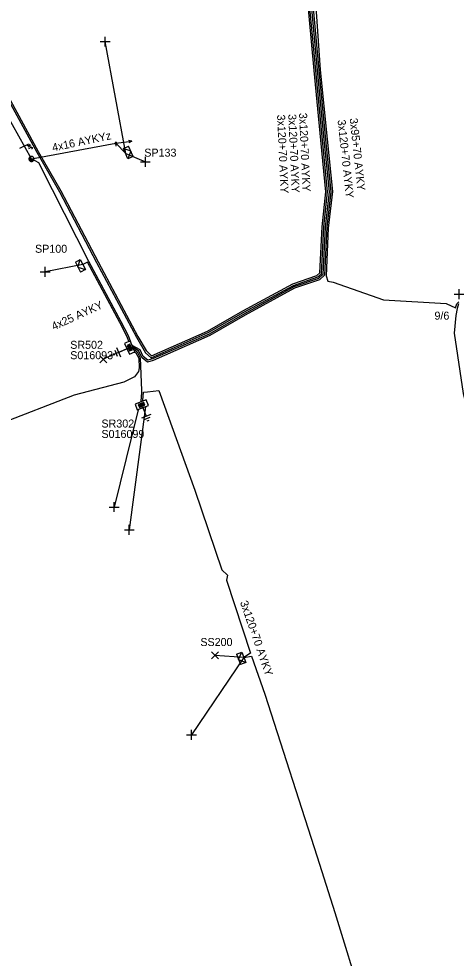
# Model space of a CAD drawing. Extents: x -717562 to -713845, y -1151196 to -1143903.
# Drawn here: x -717035.8 to -716981.2, y -1144669.5 to -1144552.1 of the extents above; entities that cross this region are included whole.
import ezdxf

# ---------------------------------------------------------------- set-up
doc = ezdxf.new("R2010")
doc.units = 0
for name, color, linetype in [('Vrstva 1', 7, 'Continuous'), ('Vrstva 12', 7, 'Continuous'), ('Vrstva 13', 7, 'Continuous'), ('Vrstva 14', 7, 'Continuous'), ('Vrstva 15', 7, 'Continuous'), ('Vrstva 18', 7, 'Continuous'), ('Vrstva 2', 7, 'Continuous'), ('Vrstva 28', 7, 'Continuous'), ('Vrstva 29', 7, 'Continuous'), ('Vrstva 30', 7, 'Continuous'), ('Vrstva 31', 7, 'Continuous'), ('Vrstva 33', 7, 'Continuous'), ('Vrstva 34', 7, 'Continuous'), ('Vrstva 5', 7, 'Continuous'), ('Vrstva 52', 7, 'Continuous'), ('Vrstva 54', 7, 'Continuous'), ('Vrstva 55', 7, 'Continuous'), ('Vrstva 59', 7, 'Continuous'), ('Vrstva 6', 7, 'Continuous'), ('Vrstva 8', 7, 'Continuous'), ('Vrstva 9', 7, 'Continuous')]:
    doc.layers.add(name, color=color, linetype=linetype)

# ---------------------------------------------------------------- blocks, each defined once
blk = doc.blocks.new('NN440')
at = {"layer": 'Vrstva 2'}
for points in [[(0.63, 0), (0.63, 0.06), (0.62, 0.13), (0.6, 0.19), (0.58, 0.25), (0.55, 0.31), (0.51, 0.37), (0.47, 0.42), (0.42, 0.46), (0.37, 0.51), (0.32, 0.54), (0.26, 0.57), (0.2, 0.59), (0.13, 0.61), (0.07, 0.62), (0, 0.63), (-0.06, 0.62), (-0.13, 0.61), (-0.19, 0.59), (-0.26, 0.57), (-0.31, 0.54), (-0.37, 0.51), (-0.42, 0.46), (-0.47, 0.42), (-0.51, 0.37), (-0.54, 0.31), (-0.57, 0.25), (-0.6, 0.19), (-0.62, 0.13), (-0.63, 0.06), (-0.63, 0), (-0.63, -0.07), (-0.62, -0.14), (-0.6, -0.2), (-0.57, -0.26), (-0.54, -0.32), (-0.51, -0.37), (-0.47, -0.43), (-0.42, -0.47), (-0.37, -0.51), (-0.31, -0.55), (-0.26, -0.58), (-0.19, -0.6), (-0.13, -0.62), (-0.06, -0.63), (0, -0.63), (0.07, -0.63), (0.13, -0.62), (0.2, -0.6), (0.26, -0.58), (0.32, -0.55), (0.37, -0.51), (0.42, -0.47), (0.47, -0.43), (0.51, -0.37), (0.55, -0.32), (0.58, -0.26), (0.6, -0.2), (0.62, -0.14), (0.63, -0.07), (0.63, 0)], [(-0.63, 0), (0.63, 0)], [(-0.6, -0.18), (0.57, -0.18)], [(-0.51, -0.32), (0.5, -0.32)], [(-0.37, -0.47), (0.35, -0.47)]]:
    blk.add_lwpolyline(points, dxfattribs=at)
blk = doc.blocks.new('NN560')
at = {"layer": 'Vrstva 2'}
for points in [[(2, 0), (1.59, 0.14)], [(0, 0), (2, 0)], [(2, 0), (1.59, -0.13)]]:
    blk.add_lwpolyline(points, dxfattribs=at)
blk = doc.blocks.new('NN840')
at = {"layer": 'Vrstva 15'}
for points in [[(0, 0.62), (0, -0.63)], [(-0.75, -0.71), (-0.75, -0.66)], [(-0.73, -0.76), (-0.75, -0.71)], [(-0.66, -0.8), (-0.73, -0.76)], [(-0.63, -0.8), (-0.66, -0.8)], [(-0.56, -0.76), (-0.63, -0.8)], [(-0.54, -0.71), (-0.56, -0.76)], [(-0.54, -0.38), (-0.54, -0.71)], [(-0.33, -0.38), (-0.33, -0.8)], [(-0.33, -0.64), (-0.13, -0.38)], [(-0.26, -0.56), (-0.09, -0.8)]]:
    blk.add_lwpolyline(points, dxfattribs=at)
blk = doc.blocks.new('NN800')
at = {"layer": 'Vrstva 1'}
for points in [[(-0.44, 0.44), (0.44, -0.44)], [(-0.44, -0.44), (0.44, 0.44)]]:
    blk.add_lwpolyline(points, dxfattribs=at)
blk = doc.blocks.new('NN620')
at = {"layer": 'Vrstva 8'}
for points in [[(0.75, 0), (-0.75, 0)], [(-0.75, 0), (-0.75, -0.75)], [(0.75, -0.75), (0.75, 0)], [(-0.75, -0.75), (0.75, -0.75)], [(0.37, -0.18), (-0.38, -0.18)], [(-0.38, -0.18), (-0.38, -0.56)], [(-0.38, -0.56), (0.37, -0.56)], [(0.32, -0.23), (-0.33, -0.23)], [(-0.33, -0.23), (-0.33, -0.51)], [(-0.33, -0.51), (0.32, -0.51)], [(0.27, -0.27), (-0.28, -0.27)], [(-0.28, -0.27), (-0.28, -0.46)], [(-0.28, -0.46), (0.27, -0.46)], [(0.23, -0.32), (-0.23, -0.32)], [(-0.23, -0.32), (-0.23, -0.42)], [(-0.23, -0.42), (0.23, -0.42)], [(-0.19, -0.37), (0.19, -0.37)], [(0.23, -0.42), (0.23, -0.32)], [(0.27, -0.46), (0.27, -0.27)], [(0.32, -0.51), (0.32, -0.23)], [(0.37, -0.56), (0.37, -0.18)]]:
    blk.add_lwpolyline(points, dxfattribs=at)
blk = doc.blocks.new('NN630')
at = {"layer": 'Vrstva 9'}
for points in [[(0, -0.7), (-0.7, 0)], [(-0.7, -0.7), (-0.7, 0), (0.7, 0), (0.7, -0.7)], [(-0.7, -0.7), (0.7, -0.7)], [(0, -0.7), (0.7, 0)]]:
    blk.add_lwpolyline(points, dxfattribs=at)
blk = doc.blocks.new('NN810')
at = {"layer": 'Vrstva 14'}
for points in [[(0, -0.64), (0, -1.89)], [(0.63, -1.89), (-0.62, -1.89)], [(0.39, -2.2), (-0.4, -2.2)], [(0, -2.52), (-0.12, -2.52)], [(0.14, -2.52), (0, -2.52)]]:
    blk.add_lwpolyline(points, dxfattribs=at)
blk = doc.blocks.new('NN500')
at = {"layer": 'Vrstva 2'}
for points in [[(0, -0.24), (0.02, -0.23), (0.05, -0.23), (0.07, -0.22), (0.09, -0.22), (0.12, -0.2), (0.14, -0.19), (0.16, -0.18), (0.17, -0.16), (0.19, -0.14), (0.2, -0.12), (0.21, -0.1), (0.22, -0.07), (0.23, -0.05), (0.23, -0.02), (0.23, 0), (0.23, 0.02), (0.23, 0.05), (0.22, 0.07), (0.21, 0.1), (0.2, 0.12), (0.19, 0.14), (0.17, 0.16), (0.16, 0.17), (0.14, 0.19), (0.12, 0.2), (0.09, 0.21), (0.07, 0.22), (0.05, 0.23), (0.02, 0.23), (0, 0.23), (-0.03, 0.23), (-0.05, 0.23), (-0.07, 0.22), (-0.1, 0.21), (-0.12, 0.2), (-0.14, 0.19), (-0.16, 0.17), (-0.18, 0.16), (-0.19, 0.14), (-0.2, 0.12), (-0.22, 0.1), (-0.22, 0.07), (-0.23, 0.05), (-0.23, 0.02), (-0.24, 0), (-0.23, -0.02), (-0.23, -0.05), (-0.22, -0.07), (-0.22, -0.1), (-0.2, -0.12), (-0.19, -0.14), (-0.18, -0.16), (-0.16, -0.18), (-0.14, -0.19), (-0.12, -0.2), (-0.1, -0.22), (-0.07, -0.22), (-0.05, -0.23), (-0.03, -0.23), (0, -0.24)], [(0, -0.24), (0.02, -0.23), (0.05, -0.23), (0.07, -0.22), (0.09, -0.22), (0.12, -0.2), (0.14, -0.19), (0.16, -0.18), (0.17, -0.16), (0.19, -0.14), (0.2, -0.12), (0.21, -0.1), (0.22, -0.07), (0.23, -0.05), (0.23, -0.02), (0.23, 0), (0.23, 0.02), (0.23, 0.05), (0.22, 0.07), (0.21, 0.1), (0.2, 0.12), (0.19, 0.14), (0.17, 0.16), (0.16, 0.17), (0.14, 0.19), (0.12, 0.2), (0.09, 0.21), (0.07, 0.22), (0.05, 0.23), (0.02, 0.23), (0, 0.23), (-0.03, 0.23), (-0.05, 0.23), (-0.07, 0.22), (-0.1, 0.21), (-0.12, 0.2), (-0.14, 0.19), (-0.16, 0.17), (-0.18, 0.16), (-0.19, 0.14), (-0.2, 0.12), (-0.22, 0.1), (-0.22, 0.07), (-0.23, 0.05), (-0.23, 0.02), (-0.24, 0), (-0.23, -0.02), (-0.23, -0.05), (-0.22, -0.07), (-0.22, -0.1), (-0.2, -0.12), (-0.19, -0.14), (-0.18, -0.16), (-0.16, -0.18), (-0.14, -0.19), (-0.12, -0.2), (-0.1, -0.22), (-0.07, -0.22), (-0.05, -0.23), (-0.03, -0.23), (0, -0.24)], [(0, -0.21), (0.02, -0.2), (0.04, -0.2), (0.06, -0.2), (0.08, -0.19), (0.1, -0.18), (0.12, -0.17), (0.14, -0.15), (0.15, -0.14), (0.16, -0.12), (0.18, -0.1), (0.19, -0.08), (0.19, -0.06), (0.2, -0.04), (0.2, -0.02), (0.2, 0), (0.2, 0.02), (0.2, 0.04), (0.19, 0.06), (0.19, 0.08), (0.18, 0.1), (0.16, 0.12), (0.15, 0.14), (0.14, 0.15), (0.12, 0.17), (0.1, 0.18), (0.08, 0.19), (0.06, 0.19), (0.04, 0.2), (0.02, 0.2), (0, 0.2), (-0.02, 0.2), (-0.04, 0.2), (-0.06, 0.19), (-0.08, 0.19), (-0.1, 0.18), (-0.12, 0.17), (-0.14, 0.15), (-0.15, 0.14), (-0.17, 0.12), (-0.18, 0.1), (-0.19, 0.08), (-0.2, 0.06), (-0.2, 0.04), (-0.21, 0.02), (-0.21, 0), (-0.21, -0.02), (-0.2, -0.04), (-0.2, -0.06), (-0.19, -0.08), (-0.18, -0.1), (-0.17, -0.12), (-0.15, -0.14), (-0.14, -0.15), (-0.12, -0.17), (-0.1, -0.18), (-0.08, -0.19), (-0.06, -0.2), (-0.04, -0.2), (-0.02, -0.2), (0, -0.21)], [(0, -0.18), (0.02, -0.18), (0.04, -0.17), (0.05, -0.17), (0.07, -0.16), (0.09, -0.15), (0.1, -0.14), (0.12, -0.13), (0.13, -0.12), (0.14, -0.1), (0.15, -0.09), (0.16, -0.07), (0.17, -0.05), (0.17, -0.04), (0.17, -0.02), (0.17, 0), (0.17, 0.02), (0.17, 0.04), (0.17, 0.05), (0.16, 0.07), (0.15, 0.09), (0.14, 0.1), (0.13, 0.12), (0.12, 0.13), (0.1, 0.14), (0.09, 0.15), (0.07, 0.16), (0.05, 0.17), (0.04, 0.17), (0.02, 0.17), (0, 0.18), (-0.02, 0.17), (-0.04, 0.17), (-0.06, 0.17), (-0.07, 0.16), (-0.09, 0.15), (-0.1, 0.14), (-0.12, 0.13), (-0.13, 0.12), (-0.14, 0.1), (-0.15, 0.09), (-0.16, 0.07), (-0.17, 0.05), (-0.17, 0.04), (-0.18, 0.02), (-0.18, 0), (-0.18, -0.02), (-0.17, -0.04), (-0.17, -0.05), (-0.16, -0.07), (-0.15, -0.09), (-0.14, -0.1), (-0.13, -0.12), (-0.12, -0.13), (-0.1, -0.14), (-0.09, -0.15), (-0.07, -0.16), (-0.06, -0.17), (-0.04, -0.17), (-0.02, -0.18), (0, -0.18)], [(0, -0.15), (0.01, -0.15), (0.03, -0.14), (0.04, -0.14), (0.06, -0.13), (0.07, -0.13), (0.08, -0.12), (0.1, -0.11), (0.11, -0.1), (0.12, -0.09), (0.13, -0.07), (0.13, -0.06), (0.14, -0.05), (0.14, -0.03), (0.14, -0.02), (0.14, 0), (0.14, 0.01), (0.14, 0.03), (0.14, 0.04), (0.13, 0.06), (0.13, 0.07), (0.12, 0.09), (0.11, 0.1), (0.1, 0.11), (0.08, 0.12), (0.07, 0.13), (0.06, 0.13), (0.04, 0.14), (0.03, 0.14), (0.01, 0.14), (0, 0.15), (-0.02, 0.14), (-0.03, 0.14), (-0.05, 0.14), (-0.06, 0.13), (-0.07, 0.13), (-0.09, 0.12), (-0.1, 0.11), (-0.11, 0.1), (-0.12, 0.09), (-0.13, 0.07), (-0.13, 0.06), (-0.14, 0.04), (-0.14, 0.03), (-0.15, 0.01), (-0.15, 0), (-0.15, -0.02), (-0.14, -0.03), (-0.14, -0.05), (-0.13, -0.06), (-0.13, -0.07), (-0.12, -0.09), (-0.11, -0.1), (-0.1, -0.11), (-0.09, -0.12), (-0.07, -0.13), (-0.06, -0.13), (-0.05, -0.14), (-0.03, -0.14), (-0.02, -0.15), (0, -0.15)], [(0, -0.12), (0.01, -0.12), (0.02, -0.11), (0.03, -0.11), (0.05, -0.11), (0.06, -0.1), (0.07, -0.09), (0.08, -0.09), (0.09, -0.08), (0.09, -0.07), (0.1, -0.06), (0.11, -0.05), (0.11, -0.04), (0.11, -0.02), (0.11, -0.01), (0.12, 0), (0.11, 0.01), (0.11, 0.02), (0.11, 0.04), (0.11, 0.05), (0.1, 0.06), (0.09, 0.07), (0.09, 0.08), (0.08, 0.09), (0.07, 0.09), (0.06, 0.1), (0.05, 0.11), (0.03, 0.11), (0.02, 0.11), (0.01, 0.12), (0, 0.12), (-0.01, 0.12), (-0.03, 0.11), (-0.04, 0.11), (-0.05, 0.11), (-0.06, 0.1), (-0.07, 0.09), (-0.08, 0.09), (-0.09, 0.08), (-0.1, 0.07), (-0.1, 0.06), (-0.11, 0.05), (-0.11, 0.04), (-0.12, 0.02), (-0.12, 0.01), (-0.12, 0), (-0.12, -0.01), (-0.12, -0.02), (-0.11, -0.04), (-0.11, -0.05), (-0.1, -0.06), (-0.1, -0.07), (-0.09, -0.08), (-0.08, -0.09), (-0.07, -0.09), (-0.06, -0.1), (-0.05, -0.11), (-0.04, -0.11), (-0.03, -0.11), (-0.01, -0.12), (0, -0.12)], [(0, -0.09), (0.01, -0.09), (0.02, -0.09), (0.03, -0.08), (0.03, -0.08), (0.04, -0.08), (0.05, -0.07), (0.06, -0.07), (0.06, -0.06), (0.07, -0.05), (0.07, -0.04), (0.08, -0.04), (0.08, -0.03), (0.08, -0.02), (0.09, -0.01), (0.09, 0), (0.09, 0.01), (0.08, 0.02), (0.08, 0.03), (0.08, 0.03), (0.07, 0.04), (0.07, 0.05), (0.06, 0.06), (0.06, 0.06), (0.05, 0.07), (0.04, 0.07), (0.03, 0.08), (0.03, 0.08), (0.02, 0.08), (0.01, 0.09), (0, 0.09), (-0.01, 0.09), (-0.02, 0.08), (-0.03, 0.08), (-0.04, 0.08), (-0.04, 0.07), (-0.05, 0.07), (-0.06, 0.06), (-0.07, 0.06), (-0.07, 0.05), (-0.08, 0.04), (-0.08, 0.03), (-0.08, 0.03), (-0.09, 0.02), (-0.09, 0.01), (-0.09, 0), (-0.09, -0.01), (-0.09, -0.02), (-0.08, -0.03), (-0.08, -0.04), (-0.08, -0.04), (-0.07, -0.05), (-0.07, -0.06), (-0.06, -0.07), (-0.05, -0.07), (-0.04, -0.08), (-0.04, -0.08), (-0.03, -0.08), (-0.02, -0.09), (-0.01, -0.09), (0, -0.09)], [(0, -0.06), (0, -0.06), (0.01, -0.06), (0.02, -0.05), (0.02, -0.05), (0.03, -0.05), (0.03, -0.05), (0.04, -0.04), (0.04, -0.04), (0.05, -0.03), (0.05, -0.03), (0.05, -0.02), (0.05, -0.02), (0.05, -0.01), (0.06, -0.01), (0.06, 0), (0.06, 0.01), (0.05, 0.01), (0.05, 0.02), (0.05, 0.02), (0.05, 0.03), (0.05, 0.03), (0.04, 0.04), (0.04, 0.04), (0.03, 0.05), (0.03, 0.05), (0.02, 0.05), (0.02, 0.05), (0.01, 0.06), (0, 0.06), (0, 0.06), (-0.01, 0.06), (-0.01, 0.06), (-0.02, 0.05), (-0.02, 0.05), (-0.03, 0.05), (-0.03, 0.05), (-0.04, 0.04), (-0.04, 0.04), (-0.05, 0.03), (-0.05, 0.03), (-0.05, 0.02), (-0.06, 0.02), (-0.06, 0.01), (-0.06, 0.01), (-0.06, 0), (-0.06, -0.01), (-0.06, -0.01), (-0.06, -0.02), (-0.05, -0.02), (-0.05, -0.03), (-0.05, -0.03), (-0.04, -0.04), (-0.04, -0.04), (-0.03, -0.05), (-0.03, -0.05), (-0.02, -0.05), (-0.02, -0.05), (-0.01, -0.06), (-0.01, -0.06), (0, -0.06)], [(0, -0.03), (0, -0.03), (0, -0.03), (0.01, -0.03), (0.01, -0.03), (0.01, -0.02), (0.02, -0.02), (0.02, -0.02), (0.02, -0.02), (0.02, -0.02), (0.02, -0.01), (0.02, -0.01), (0.03, -0.01), (0.03, -0.01), (0.03, 0), (0.03, 0), (0.03, 0), (0.03, 0.01), (0.03, 0.01), (0.02, 0.01), (0.02, 0.01), (0.02, 0.02), (0.02, 0.02), (0.02, 0.02), (0.02, 0.02), (0.01, 0.02), (0.01, 0.02), (0.01, 0.03), (0, 0.03), (0, 0.03), (0, 0.03), (0, 0.03), (-0.01, 0.03), (-0.01, 0.03), (-0.01, 0.02), (-0.02, 0.02), (-0.02, 0.02), (-0.02, 0.02), (-0.02, 0.02), (-0.02, 0.02), (-0.03, 0.01), (-0.03, 0.01), (-0.03, 0.01), (-0.03, 0.01), (-0.03, 0), (-0.03, 0), (-0.03, 0), (-0.03, -0.01), (-0.03, -0.01), (-0.03, -0.01), (-0.03, -0.01), (-0.02, -0.02), (-0.02, -0.02), (-0.02, -0.02), (-0.02, -0.02), (-0.02, -0.02), (-0.01, -0.03), (-0.01, -0.03), (-0.01, -0.03), (0, -0.03), (0, -0.03)], [(0.23, 0), (0.7, 0)]]:
    blk.add_lwpolyline(points, dxfattribs=at)

msp = doc.modelspace()

# ---------------------------------------------------------------- linework, layer by layer
at = {"layer": 'Vrstva 1'}
msp.add_lwpolyline([(-717034.22, -1144569.65), (-717039.77, -1144559.73), (-717050.99, -1144539.38), (-717063.54, -1144519.5)], dxfattribs=at)
at = {"layer": 'Vrstva 5'}
for points in [[(-717040.82, -1144555.52), (-717033.55, -1144568.82), (-717030.73, -1144573.76), (-717026.08, -1144582.6), (-717021.12, -1144591.94), (-717019.98, -1144593.88), (-717019.27, -1144594.49), (-717012.14, -1144591.35), (-717007.71, -1144588.82), (-717001.52, -1144585.46), (-716998.47, -1144584.4), (-716998.01, -1144584), (-716997.73, -1144578.15), (-716997.25, -1144573.76), (-716997.9, -1144567.29), (-716998.73, -1144558.59), (-716999.61, -1144549.04)], [(-717040.64, -1144555.42), (-717033.37, -1144568.72), (-717030.55, -1144573.66), (-717025.9, -1144582.51), (-717020.94, -1144591.84), (-717019.91, -1144593.6), (-717019.24, -1144594.25), (-717012.23, -1144591.17), (-717007.81, -1144588.65), (-717001.6, -1144585.27), (-716998.57, -1144584.23), (-716998.21, -1144583.9), (-716997.93, -1144578.14), (-716997.45, -1144573.76), (-716998.09, -1144567.31), (-716998.92, -1144558.61), (-716999.8, -1144549.06)], [(-716999.41, -1144549.02), (-716998.53, -1144558.57), (-716997.7, -1144567.27), (-716997.05, -1144573.76), (-716997.53, -1144578.17), (-716997.82, -1144584.09), (-716998.37, -1144584.58), (-717001.44, -1144585.64), (-717007.62, -1144589), (-717012.05, -1144591.53), (-717019.1, -1144594.64), (-717019.67, -1144594.82), (-717020.26, -1144594.35), (-717020.66, -1144593.51), (-717021.64, -1144592.98)], [(-716999.21, -1144549), (-716998.33, -1144558.55), (-716997.5, -1144567.25), (-716996.85, -1144573.76), (-716997.33, -1144578.18), (-716997.62, -1144584.18), (-716998.26, -1144584.75), (-717001.36, -1144585.82), (-717007.52, -1144589.17), (-717011.96, -1144591.71), (-717019.03, -1144594.83), (-717019.71, -1144595.04), (-717020.4, -1144594.49), (-717020.85, -1144593.64), (-717021.57, -1144593.19)], [(-716998.85, -1144548.8), (-716998.18, -1144558.5), (-716997.3, -1144567.18), (-716996.65, -1144573.74), (-716997.16, -1144578.29), (-716997.44, -1144584.25), (-716997.21, -1144584.93), (-716996.53, -1144585.06), (-716990.27, -1144587.27), (-716982.45, -1144587.7), (-716981.28, -1144588.24), (-716981.11, -1144587.75), (-716980.86, -1144587.51)], [(-717021.7, -1144592.9), (-717021.8, -1144592.55), (-717022.12, -1144591.74), (-717023.01, -1144589.99), (-717027.07, -1144582.45), (-717031.58, -1144573.5), (-717033.29, -1144570.15), (-717034.22, -1144569.65)], [(-716980.89, -1144587.78), (-716981.08, -1144588.33), (-716981.25, -1144589.23), (-716981.44, -1144591.44), (-716980.33, -1144598.95), (-716978.44, -1144606.72), (-716976.15, -1144615.72), (-716974.11, -1144620.38), (-716970.22, -1144627.02), (-716966.72, -1144631.93), (-716960.84, -1144636.42), (-716951.85, -1144640.96), (-716944.34, -1144644.49), (-716944.02, -1144644.29), (-716943.9, -1144644.06)], [(-717021.48, -1144593.39), (-717021.02, -1144593.76), (-717020.63, -1144594.51), (-717020.47, -1144598.61), (-717020.46, -1144598.84), (-717020.58, -1144599.92)], [(-717020.32, -1144599.86), (-717020.21, -1144598.81), (-717019.74, -1144598.76), (-717018.31, -1144598.61), (-717013.81, -1144611.06), (-717010.43, -1144620.99), (-717009.74, -1144621.66), (-717009.87, -1144622.3), (-717006.87, -1144631.41), (-717007.7, -1144631.94), (-717006.74, -1144631.79), (-717005.1, -1144636.53), (-716998.54, -1144656.86), (-716996.34, -1144663.81), (-716992.87, -1144675.06), (-716994.15, -1144675.65), (-716992.75, -1144675.44), (-716988.59, -1144688.58), (-716988.29, -1144690.68)]]:
    msp.add_lwpolyline(points, dxfattribs=at)
at = {"layer": 'Vrstva 52'}
for points in [[(-717022.02, -1144592.53), (-717022.3, -1144591.82), (-717023.18, -1144590.08), (-717027.24, -1144582.54), (-717027.79, -1144582.86)], [(-717021.42, -1144593.75), (-717021.18, -1144593.89), (-717020.83, -1144594.57), (-717020.79, -1144595.76), (-717020.86, -1144596.22), (-717021.37, -1144596.88), (-717022.69, -1144597.53), (-717028.89, -1144599.19), (-717038.39, -1144602.82), (-717045.77, -1144606.24), (-717053.05, -1144610.53), (-717061.1, -1144615.47), (-717070.72, -1144619.35), (-717075.45, -1144621.46), (-717082.85, -1144625.28), (-717086.3, -1144627.19), (-717090.15, -1144629.48), (-717089.68, -1144631.29)]]:
    msp.add_lwpolyline(points, dxfattribs=at)
at = {"layer": 'Vrstva 54'}
msp.add_lwpolyline([(-717034.22, -1144569.65), (-717023.67, -1144567.7), (-717022.45, -1144568.98)], dxfattribs=at)
at = {"layer": 'Vrstva 59'}
for points in [[(-717022.45, -1144568.98), (-717025, -1144555)], [(-717022.45, -1144568.98), (-717020, -1144570)], [(-717027.79, -1144582.86), (-717032.52, -1144583.77)], [(-717022.4, -1144593.43), (-717025.26, -1144594.69)], [(-717020.88, -1144600.99), (-717023.88, -1144613.15)], [(-717019.96, -1144600.64), (-717022, -1144616)], [(-717007.7, -1144631.94), (-717011.31, -1144631.7)], [(-717007.7, -1144631.94), (-717014.25, -1144641.63)]]:
    msp.add_lwpolyline(points, dxfattribs=at)

# ---------------------------------------------------------------- block references
at = {"layer": 'Vrstva 13', "xscale": 0.5}
for name, p, yscale, rotation in [('NN500', (-717023.67, -1144567.7), 0.5, -90), ('NN440', (-717034.22, -1144569.65), 0.5000000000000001, -61.813255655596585)]:
    msp.add_blockref(name, p, dxfattribs=dict(at, yscale=yscale, rotation=rotation))
at = {"layer": 'Vrstva 13', "rotation": 7.181242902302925}
msp.add_blockref('NN560', (-717023.67, -1144567.7), dxfattribs=at)
at = {"layer": 'Vrstva 15'}
for p, rotation in [((-717021.6, -1144593.08), -66.20335828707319), ((-717020.59, -1144600.04), 21.03998890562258)]:
    msp.add_blockref('NN810', p, dxfattribs=dict(at, rotation=rotation))
at = {"layer": 'Vrstva 18', "rotation": 116.57694450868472}
msp.add_blockref('NN840', (-717035.13, -1144568.03), dxfattribs=at)
at = {"layer": 'Vrstva 28'}
for p, rotation in [((-717021.6, -1144593.08), -66.20335828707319), ((-717020.59, -1144600.04), 21.039988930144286)]:
    msp.add_blockref('NN620', p, dxfattribs=dict(at, rotation=rotation))
at = {"layer": 'Vrstva 31'}
for p, rotation in [((-717022.45, -1144568.98), 113.25964720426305), ((-717027.79, -1144582.86), -62.13793403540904), ((-717007.7, -1144631.94), -69.16444441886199)]:
    msp.add_blockref('NN630', p, dxfattribs=dict(at, rotation=rotation))
at = {"layer": 'Vrstva 34'}
for p, rotation in [((-717025, -1144555), 45), ((-717020, -1144570), 45), ((-717032.52, -1144583.77), 44.99999995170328), ((-716980.81, -1144586.54), 45.00000009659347), ((-717023.88, -1144613.15), 45), ((-717022, -1144616), 45), ((-717014.25, -1144641.63), 45)]:
    msp.add_blockref('NN800', p, dxfattribs=dict(at, rotation=rotation))
for p in [(-717025.26, -1144594.69), (-717011.31, -1144631.7)]:
    msp.add_blockref('NN800', p, dxfattribs=at)

# ---------------------------------------------------------------- texts
at = {"layer": 'Vrstva 12'}
msp.add_text('9/6', height=1, dxfattribs=at).set_placement((-716983.9, -1144589.74))
at = {"layer": 'Vrstva 29'}
for s, p in [('S016093', (-717029.38, -1144594.68)), ('S016099', (-717025.48, -1144604.52))]:
    msp.add_text(s, height=1, dxfattribs=at).set_placement(p)
at = {"layer": 'Vrstva 30'}
for s, p in [('SR502', (-717029.38, -1144593.38)), ('SR302', (-717025.48, -1144603.22))]:
    msp.add_text(s, height=1, dxfattribs=at).set_placement(p)
at = {"layer": 'Vrstva 33'}
for s, p in [('SP133', (-717020.13, -1144569.37)), ('SP100', (-717033.77, -1144581.38)), ('SS200', (-717013.13, -1144630.52))]:
    msp.add_text(s, height=1, dxfattribs=at).set_placement(p)
at = {"layer": 'Vrstva 54'}
msp.add_text('4x25 AYKY', height=1, rotation=24.414, dxfattribs=at).set_placement((-717031.44, -1144591.09))
at = {"layer": 'Vrstva 55'}
msp.add_text('4x16 AYKYz', height=1, rotation=12.014, dxfattribs=at).set_placement((-717031.53, -1144568.74))
at = {"layer": 'Vrstva 6'}
for s, rotation, p in [('3x120+70 AYKY', 272.565, (-717003.55, -1144564.14)), ('3x120+70 AYKY', 272.564, (-717002.16, -1144564.07)), ('3x120+70 AYKY', 272.564, (-717000.81, -1144563.92)), ('3x120+70 AYKY', 276.106, (-716996, -1144564.8)), ('3x95+70 AYKY', 276.106, (-716994.49, -1144564.6)), ('3x120+70 AYKY', 289.056, (-717008.19, -1144625.05))]:
    msp.add_text(s, height=1, rotation=rotation, dxfattribs=at).set_placement(p)

doc.saveas('drawing.dxf')
